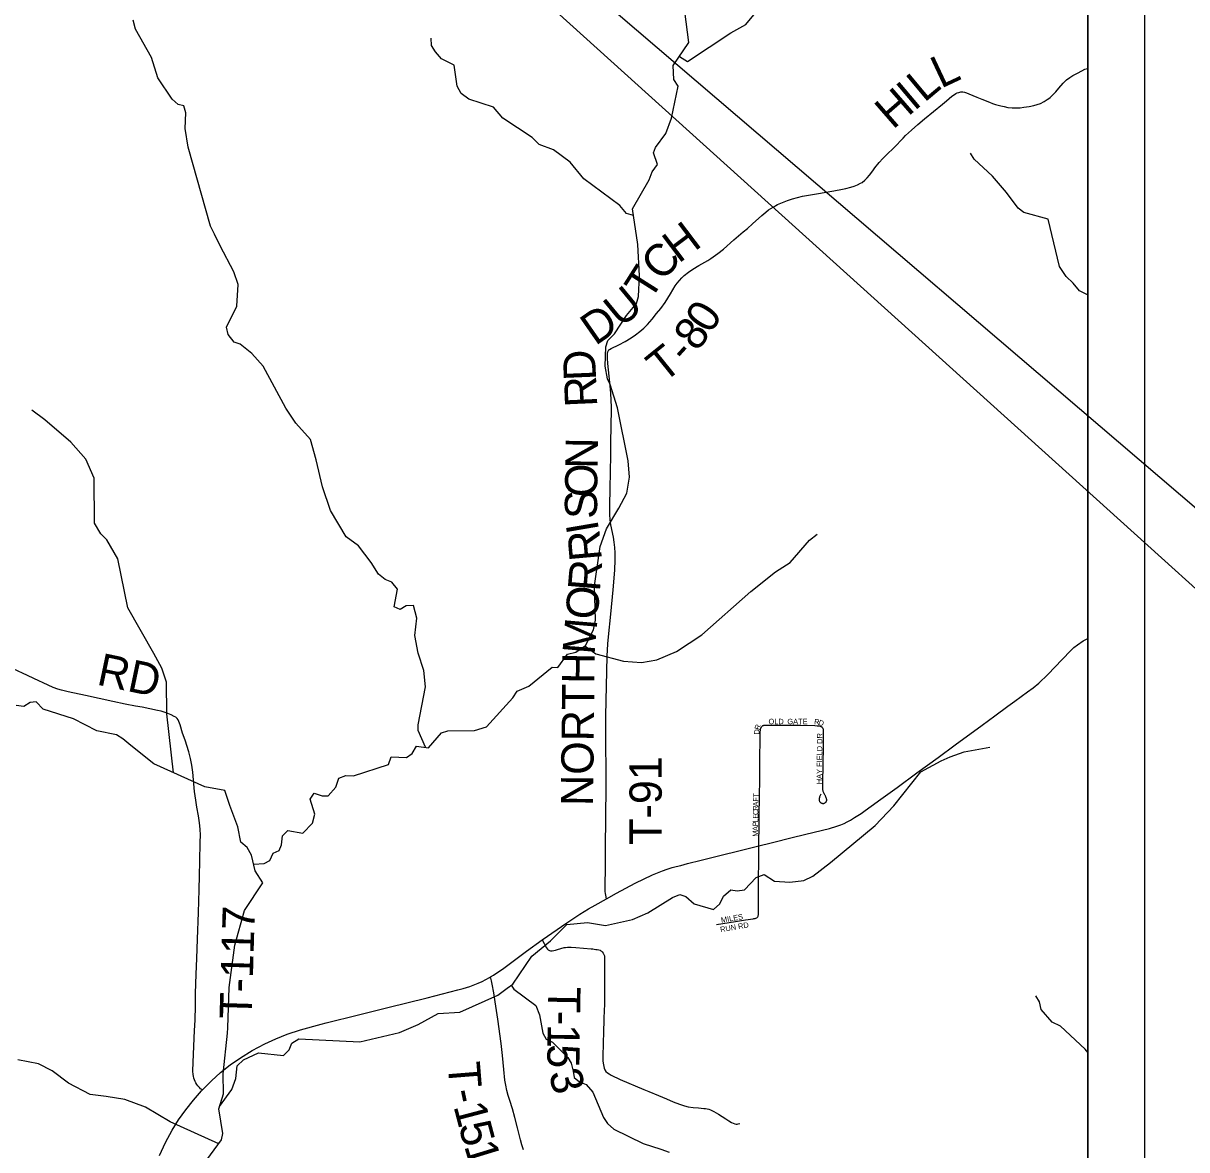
# Model space of a CAD drawing. Extents: x 0 to 34, y 0 to 22.
# Drawn here: x 7.525 to 9.575, y 16.31 to 18.295 of the extents above; entities that cross this region are included whole.
import ezdxf

# ---------------------------------------------------------------- set-up
doc = ezdxf.new("R2010")
doc.units = 0
for name, color, linetype in [('GM_X_County', 7, 'Continuous'), ('GM_X_Minor_River', 7, 'Continuous'), ('GM_X_State_Route', 7, 'Continuous'), ('GM_X_Township', 7, 'Continuous'), ('GM_X_Township_Road', 7, 'Continuous'), ('GM_X_Township_Road_Text', 7, 'Continuous'), ('GM_X_Township_Subdivision', 7, 'Continuous'), ('GM_X_Township_Subdivision_Text', 7, 'Continuous'), ('SH_Data', 7, 'Continuous')]:
    doc.layers.add(name, color=color, linetype=linetype)

msp = doc.modelspace()

# ---------------------------------------------------------------- linework, layer by layer
at = {"layer": 'GM_X_County'}
msp.add_lwpolyline([(7.0736, 21.2003), (2.6013, 21.2003), (2.6013, 14.4003), (9.4013, 14.4003), (9.4013, 21.1598)], dxfattribs=at)
at = {"layer": 'GM_X_Minor_River'}
for points in [[(8.6808, 18.2367), (8.6953, 18.228), (8.7713, 18.2784), (8.7977, 18.2929), (8.8207, 18.3207), (8.8495, 18.3402), (8.8638, 18.3467), (8.8752, 18.3479), (8.8881, 18.3521), (8.9145, 18.3738), (8.9303, 18.4008), (8.9544, 18.4256), (9.0262, 18.4749), (9.0455, 18.4962), (9.0612, 18.5312), (9.0657, 18.5441), (9.0807, 18.576), (9.1045, 18.5996), (9.1615, 18.6431), (9.1725, 18.6477)], [(7.9306, 16.8132), (7.9492, 16.8148), (7.959, 16.8197), (7.965, 16.8327), (7.9756, 16.8377), (7.9797, 16.8475), (7.9812, 16.8635), (7.991, 16.873), (8.0175, 16.8678), (8.0345, 16.8857), (8.0386, 16.9017), (8.0301, 16.9282), (8.0373, 16.9385), (8.0513, 16.9336), (8.0619, 16.9337), (8.0751, 16.9493), (8.0804, 16.9649), (8.0932, 16.9698), (8.1065, 16.9691), (8.1682, 16.9888), (8.1727, 17.0028), (8.1996, 17.0014), (8.2098, 17.0083), (8.2177, 17.0216), (8.2389, 17.0187), (8.2615, 17.045), (8.2725, 17.0484), (8.3195, 17.0487), (8.3411, 17.0556), (8.3875, 17.1066), (8.395, 17.118), (8.4154, 17.1269), (8.4566, 17.1608), (8.4668, 17.1601), (8.4834, 17.1837), (8.4985, 17.1872), (8.5151, 17.199), (8.5294, 17.2264), (8.5331, 17.2431), (8.5309, 17.3038), (8.5409, 17.3729), (8.5525, 17.4041), (8.5743, 17.441), (8.5882, 17.4672), (8.5926, 17.4953), (8.5906, 17.5241), (8.5719, 17.6174), (8.5585, 17.6587), (8.5543, 17.6685), (8.55, 17.6912), (8.551, 17.725), (8.5547, 17.7364), (8.5664, 17.7478), (8.5875, 17.7802), (8.6052, 17.8011), (8.6086, 17.814), (8.6107, 17.8501), (8.6078, 17.9051), (8.598, 17.968), (8.6273, 18.0194), (8.6326, 18.0334), (8.642, 18.0464), (8.6354, 18.0668), (8.6388, 18.0763), (8.6569, 18.1011), (8.6666, 18.128), (8.6785, 18.1842), (8.6708, 18.1964), (8.67, 18.2206), (8.6975, 18.2613), (8.688, 18.3341)], [(8.2333, 17.0195), (8.2206, 17.049), (8.2202, 17.0592), (8.2335, 17.126), (8.2303, 17.1545), (8.2203, 17.1852), (8.2145, 17.2162), (8.2178, 17.247), (8.212, 17.2693), (8.1995, 17.2689), (8.1885, 17.262), (8.1779, 17.2669), (8.1842, 17.2981), (8.1743, 17.3105), (8.1625, 17.315), (8.1503, 17.3245), (8.1377, 17.3449), (8.1156, 17.3744), (8.0936, 17.3902), (8.0657, 17.4364), (8.0518, 17.4784), (8.0406, 17.5262), (8.031, 17.5618), (8.0047, 17.5905), (7.9872, 17.617), (7.9474, 17.6911), (7.9272, 17.7134), (7.907, 17.73), (7.8964, 17.733), (7.8857, 17.7466), (7.8827, 17.7595), (7.901, 17.7968), (7.9031, 17.8351), (7.8955, 17.857), (7.8718, 17.9032), (7.8614, 17.9233), (7.8545, 17.9377), (7.8149, 18.0767), (7.8098, 18.1097), (7.8108, 18.1374), (7.8073, 18.1495), (7.7975, 18.1521), (7.7868, 18.1616), (7.7616, 18.199), (7.7505, 18.2346), (7.7226, 18.2849), (7.7183, 18.3008)], [(8.5997, 17.9567), (8.5878, 17.96), (8.5756, 17.974), (8.5125, 18.0208), (8.4881, 18.0506), (8.4588, 18.0721), (8.4337, 18.0815), (8.4215, 18.0939), (8.3698, 18.1278), (8.3531, 18.1475), (8.3098, 18.1613), (8.2961, 18.1715), (8.2892, 18.1844), (8.2838, 18.2212), (8.2613, 18.2324), (8.2511, 18.2449), (8.2438, 18.2559), (8.2434, 18.2688)], [(9.4013, 17.8162), (9.3859, 17.8235), (9.3745, 17.8371), (9.3623, 17.8488), (9.3504, 17.8666), (9.3307, 17.95), (9.2875, 17.9616), (9.2776, 17.9691), (9.2574, 17.9967), (9.2326, 18.0255), (9.1999, 18.056), (9.1937, 18.0663)], [(7.7895, 16.9746), (7.7778, 17.0784), (7.7772, 17.1342), (7.7687, 17.1588), (7.7546, 17.1845), (7.7087, 17.2651), (7.6913, 17.3515), (7.6718, 17.3852), (7.6615, 17.3958), (7.65, 17.4143), (7.6493, 17.4936), (7.6347, 17.5269), (7.6084, 17.5571), (7.5624, 17.5964), (7.5396, 17.6137)], [(8.5143, 17.1984), (8.5334, 17.1843), (8.5823, 17.1713), (8.6142, 17.1687), (8.6411, 17.1734), (8.6755, 17.188), (8.7205, 17.2174), (8.8065, 17.2937), (8.8503, 17.3288), (8.876, 17.3448), (8.91, 17.3844), (8.9236, 17.3951)], [(7.8888, 16.9165), (7.88, 16.9431), (7.8447, 16.9497), (7.7547, 16.9903), (7.7144, 17.0223), (7.7003, 17.034), (7.6889, 17.0412), (7.6544, 17.0486), (7.6133, 17.0693), (7.5594, 17.0865), (7.5476, 17.0994), (7.5367, 17.0982), (7.5257, 17.0913), (7.512, 17.0931)], [(7.8706, 16.3864), (7.8923, 16.4165), (7.8994, 16.4359), (7.9016, 16.4583), (7.9129, 16.4686), (7.939, 16.4809), (7.983, 16.4761), (7.9932, 16.4864), (7.9976, 16.4982), (8.0101, 16.5058), (8.1174, 16.5003), (8.1878, 16.5165), (8.2207, 16.5307), (8.2555, 16.5502), (8.2941, 16.5527), (8.3607, 16.5826), (8.3773, 16.5948), (8.3871, 16.602), (8.4207, 16.6515), (8.4535, 16.6782), (8.4822, 16.7068), (8.5189, 16.7104), (8.5508, 16.7052), (8.5981, 16.7161), (8.625, 16.7279), (8.6688, 16.7547), (8.6817, 16.7597), (8.6919, 16.7563), (8.7068, 16.7435), (8.7409, 16.7338), (8.7519, 16.7437), (8.7582, 16.757), (8.7711, 16.7684), (8.7824, 16.7662), (8.7957, 16.7682), (8.8161, 16.7899), (8.8301, 16.7952), (8.8483, 16.7832), (8.8756, 16.7814), (8.8999, 16.7846), (8.9157, 16.7922), (8.9471, 16.8166), (9.026, 16.8815), (9.0588, 16.9161), (9.1063, 16.9759), (9.1418, 16.9954), (9.1577, 17.0023), (9.1823, 17.0115), (9.2278, 17.0193)], [(7.8271, 16.2637), (7.8741, 16.3277), (7.876, 16.3387), (7.8693, 16.3823), (7.8775, 16.4089), (7.877, 16.4442), (7.8846, 16.5155), (7.885, 16.525), (7.8873, 16.596), (7.8972, 16.6707), (7.9147, 16.7315), (7.9467, 16.7806), (7.9333, 16.8018), (7.9267, 16.8295), (7.9191, 16.8427), (7.9077, 16.8521), (7.9026, 16.879), (7.8888, 16.9165)], [(8.3845, 16.6001), (8.3891, 16.5933), (8.4275, 16.5643), (8.434, 16.548), (8.4402, 16.5154), (8.446, 16.5048), (8.457, 16.4999), (8.484, 16.4727), (8.4901, 16.4629), (8.4936, 16.4485), (8.4952, 16.4375), (8.5047, 16.4296), (8.5165, 16.4254), (8.5283, 16.4115), (8.547, 16.3672), (8.5539, 16.3566), (8.5653, 16.3464), (8.617, 16.3212), (8.6481, 16.3111), (8.6629, 16.3058)], [(9.4013, 16.4812), (9.3959, 16.4874), (9.3521, 16.5278), (9.3376, 16.535), (9.3182, 16.5573), (9.3151, 16.5709), (9.3086, 16.5815)], [(7.869, 16.3207), (7.7834, 16.3591), (7.7397, 16.3851), (7.7036, 16.3986), (7.6706, 16.4041), (7.6422, 16.4078), (7.6042, 16.4277), (7.5753, 16.4492), (7.5514, 16.4616), (7.5149, 16.4687)]]:
    msp.add_lwpolyline(points, dxfattribs=at)
at = {"layer": 'GM_X_State_Route'}
for points in [[(8.0585, 16.5337), (8.1156, 16.5479), (8.1668, 16.5608), (8.2362, 16.5779), (8.2904, 16.5917), (8.2997, 16.5942), (8.3112, 16.598), (8.32, 16.6011), (8.3264, 16.6039), (8.3332, 16.6068), (8.3397, 16.61), (8.346, 16.6136), (8.3479, 16.6147), (8.3534, 16.6181), (8.3714, 16.6304), (8.4113, 16.66), (8.4389, 16.6801), (8.4823, 16.7101), (8.5056, 16.7255), (8.5208, 16.7348), (8.5321, 16.7414), (8.5522, 16.7526), (8.57, 16.7625), (8.6028, 16.78), (8.6336, 16.7945), (8.6508, 16.8015), (8.6591, 16.8044), (8.6681, 16.8075), (8.6753, 16.8093), (8.6833, 16.8113), (8.6952, 16.8144), (8.719, 16.8206), (8.8206, 16.8456), (8.8427, 16.851), (8.8818, 16.8607), (8.918, 16.8696), (8.9452, 16.8763), (8.958, 16.8802), (8.965, 16.8827), (8.971, 16.885), (8.9766, 16.8879), (8.9822, 16.8912), (8.9893, 16.8954), (8.9954, 16.8992), (9.0009, 16.9026), (9.0081, 16.9078), (9.0188, 16.9157), (9.0358, 16.9278), (9.0642, 16.9486), (9.099, 16.9741), (9.137, 17.0015), (9.1669, 17.0237), (9.2143, 17.0585), (9.2368, 17.075), (9.2592, 17.0917), (9.2717, 17.1009), (9.2944, 17.117), (9.3043, 17.1244), (9.3139, 17.1324), (9.3297, 17.1474), (9.3554, 17.1743), (9.3705, 17.1898), (9.376, 17.1951), (9.3822, 17.1998), (9.3923, 17.2068), (9.4004, 17.2112), (9.4013, 17.2116)], [(7.7648, 16.3002), (7.7753, 16.3227), (7.787, 16.3446), (7.7983, 16.3631), (7.8108, 16.3808), (7.8243, 16.3978), (7.8388, 16.4139), (7.8403, 16.4155), (7.8562, 16.4315), (7.8723, 16.4461), (7.8893, 16.4596), (7.9071, 16.472), (7.9282, 16.485), (7.95, 16.4968), (7.9697, 16.5059), (7.9899, 16.5138), (8.0134, 16.5216), (8.0493, 16.5314), (8.0585, 16.5337)]]:
    msp.add_lwpolyline(points, dxfattribs=at)
at = {"layer": 'GM_X_Township'}
msp.add_line((9.4013, 16.1226), (9.4013, 21.1598), dxfattribs=at)
at = {"layer": 'GM_X_Township_Road'}
for points in [[(8.5546, 17.7165), (8.5551, 17.7176), (8.5558, 17.7188), (8.5567, 17.7197), (8.5576, 17.7205), (8.5603, 17.7221), (8.5743, 17.7287), (8.5852, 17.7347), (8.5958, 17.7411), (8.6036, 17.7462), (8.611, 17.7518), (8.618, 17.758), (8.6246, 17.7646), (8.6328, 17.7739), (8.6406, 17.7836), (8.6481, 17.7928), (8.6555, 17.8032), (8.6651, 17.8187), (8.6733, 17.8323), (8.6769, 17.8374), (8.6807, 17.8422), (8.6849, 17.8467), (8.6894, 17.8509), (8.6967, 17.8566), (8.7043, 17.8618), (8.7149, 17.8682), (8.731, 17.8774), (8.7362, 17.8807), (8.7486, 17.8897), (8.7582, 17.8974), (8.7769, 17.9135), (8.7934, 17.9274), (8.8005, 17.9335), (8.8097, 17.9417), (8.8258, 17.9564), (8.8328, 17.9625), (8.8378, 17.9662), (8.8457, 17.9712), (8.8539, 17.9756), (8.8623, 17.9795), (8.871, 17.9829), (8.8798, 17.9859), (8.8888, 17.9884), (8.8979, 17.9904), (8.9223, 17.9948), (8.9529, 18.0001), (8.9681, 18.0028), (8.9712, 18.0034), (8.9742, 18.004), (8.9831, 18.0063), (8.9889, 18.0081), (8.9946, 18.0104), (9.0001, 18.0132), (9.0027, 18.0149), (9.0076, 18.0187), (9.0119, 18.023), (9.0159, 18.0278), (9.0215, 18.0352), (9.0252, 18.0402), (9.033, 18.0498), (9.0392, 18.0567), (9.0457, 18.0634), (9.0591, 18.0764), (9.0748, 18.0926), (9.0793, 18.0975), (9.0899, 18.107), (9.1011, 18.1169), (9.1129, 18.127), (9.1441, 18.1526), (9.1512, 18.1587), (9.1607, 18.1666), (9.1655, 18.1699), (9.1679, 18.1712), (9.1704, 18.1724), (9.1732, 18.1734), (9.1767, 18.1741), (9.1799, 18.1741), (9.1831, 18.1737), (9.1866, 18.1729), (9.1908, 18.1711), (9.1977, 18.1679), (9.2047, 18.1648), (9.2138, 18.1612), (9.227, 18.1562), (9.2326, 18.154), (9.2377, 18.1523), (9.2469, 18.1496), (9.253, 18.1483), (9.2595, 18.147), (9.2674, 18.1462), (9.2744, 18.1461), (9.2815, 18.1464), (9.2878, 18.1471), (9.2968, 18.1484), (9.3055, 18.1503), (9.3114, 18.152), (9.3169, 18.1541), (9.3233, 18.1574), (9.3289, 18.1606), (9.3319, 18.1626), (9.334, 18.1644), (9.3384, 18.1688), (9.3439, 18.1746), (9.3493, 18.1809), (9.3568, 18.1899), (9.363, 18.1953), (9.3689, 18.1994), (9.3742, 18.203), (9.382, 18.2075), (9.3898, 18.2113), (9.3954, 18.2141), (9.3996, 18.2155), (9.4013, 18.2158)], [(8.5522, 16.7526), (8.5509, 16.7586), (8.5504, 16.7617), (8.5501, 16.7653), (8.55, 16.7715), (8.5501, 16.7807), (8.5503, 16.8023), (8.5504, 16.8208), (8.5504, 16.8363), (8.5507, 16.858), (8.551, 16.8797), (8.5513, 16.9106), (8.5515, 16.9354), (8.5517, 16.954), (8.5517, 16.9788), (8.5516, 16.9943), (8.5513, 17.0097), (8.5513, 17.0747), (8.5533, 17.1799), (8.5546, 17.2016), (8.5556, 17.2139), (8.56, 17.2539), (8.5642, 17.2971), (8.5667, 17.3312), (8.5675, 17.3498), (8.5675, 17.3622), (8.5671, 17.3715), (8.5661, 17.3807), (8.5646, 17.3899), (8.5599, 17.4111), (8.5586, 17.4203), (8.5579, 17.4295), (8.5579, 17.4451), (8.5585, 17.4761), (8.5592, 17.504), (8.5597, 17.535), (8.5602, 17.5598), (8.5604, 17.5815), (8.5609, 17.6186), (8.5607, 17.631), (8.5601, 17.6434), (8.5583, 17.662), (8.5548, 17.6959), (8.554, 17.7052), (8.5538, 17.7105), (8.5539, 17.7125), (8.5541, 17.7144), (8.5546, 17.7165)], [(7.8275, 16.4304), (7.8273, 16.4307), (7.8261, 16.4336), (7.8251, 16.4365), (7.8244, 16.4396), (7.8239, 16.4426), (7.8235, 16.4488), (7.8237, 16.4643), (7.8264, 16.5202), (7.8273, 16.5388), (7.8278, 16.5636), (7.8282, 16.5853), (7.8293, 16.6194), (7.8302, 16.6474), (7.8314, 16.6815), (7.8333, 16.728), (7.8344, 16.7683), (7.835, 16.7932), (7.8355, 16.818), (7.836, 16.8303), (7.8362, 16.8396), (7.8366, 16.852), (7.8368, 16.8647), (7.8363, 16.8751), (7.8352, 16.8862), (7.8331, 16.8985), (7.8305, 16.9137), (7.8287, 16.9259), (7.8266, 16.9413), (7.8233, 16.9753), (7.8218, 16.9876), (7.8192, 16.9997), (7.8162, 17.0114), (7.8097, 17.0321), (7.8052, 17.0442), (7.8008, 17.0591), (7.7988, 17.065), (7.7974, 17.0677), (7.7955, 17.0702), (7.7932, 17.0723), (7.7906, 17.0739), (7.785, 17.0765), (7.7763, 17.08), (7.7675, 17.0829), (7.7614, 17.0844), (7.7342, 17.0898), (7.7221, 17.092), (7.7039, 17.0955), (7.6826, 17.0999), (7.6342, 17.1106), (7.6038, 17.117), (7.5917, 17.1199), (7.5858, 17.1217), (7.5771, 17.125), (7.5685, 17.1287), (7.5433, 17.1404), (7.5321, 17.1457), (7.5069, 17.1579)], [(8.4389, 16.6801), (8.4424, 16.6735), (8.4464, 16.6659), (8.4482, 16.6634), (8.4494, 16.6624), (8.4506, 16.6617), (8.452, 16.6613), (8.4535, 16.6609), (8.4565, 16.6608), (8.4596, 16.6613), (8.4627, 16.662), (8.4657, 16.6629), (8.4716, 16.6648), (8.4775, 16.6664), (8.4803, 16.6668), (8.4837, 16.667), (8.4898, 16.667), (8.498, 16.6663), (8.5251, 16.6644), (8.528, 16.6641), (8.5308, 16.6636), (8.5336, 16.6632), (8.536, 16.6629), (8.5387, 16.6623), (8.541, 16.6616), (8.5422, 16.6609), (8.5432, 16.6603), (8.544, 16.6596), (8.5446, 16.6589), (8.5464, 16.6566), (8.5477, 16.6541), (8.5485, 16.6516), (8.5488, 16.6485), (8.549, 16.6456), (8.549, 16.6394), (8.5487, 16.6301), (8.5486, 16.5655), (8.5484, 16.5562), (8.5478, 16.5406), (8.547, 16.5157), (8.5466, 16.5002), (8.546, 16.4722), (8.5461, 16.466), (8.5469, 16.4598), (8.5475, 16.4567), (8.5484, 16.4538), (8.5496, 16.4509), (8.5512, 16.4483), (8.5539, 16.4459), (8.5569, 16.4439), (8.5608, 16.4415), (8.5763, 16.4342), (8.6178, 16.4166), (8.6266, 16.413), (8.6438, 16.4058), (8.658, 16.3996), (8.6695, 16.3948), (8.6811, 16.3903), (8.6899, 16.3874), (8.696, 16.3859), (8.7052, 16.3844), (8.7145, 16.3838), (8.7238, 16.3831), (8.7269, 16.3827), (8.7329, 16.3814), (8.7358, 16.3803), (8.7414, 16.3777), (8.7494, 16.373), (8.7623, 16.3645), (8.7676, 16.3613), (8.7727, 16.3583), (8.7754, 16.3571), (8.7783, 16.3561), (8.7808, 16.3555), (8.7827, 16.3555), (8.7843, 16.3556), (8.7873, 16.3564)], [(8.4062, 16.31), (8.4031, 16.3188), (8.4005, 16.3278), (8.3953, 16.3489), (8.3909, 16.3671), (8.3867, 16.382), (8.3819, 16.3968), (8.3791, 16.4057), (8.3769, 16.4147), (8.3749, 16.4238), (8.3734, 16.433), (8.3713, 16.4514), (8.3693, 16.4761), (8.3669, 16.4976), (8.3609, 16.5404), (8.3587, 16.5558), (8.3564, 16.5711), (8.3536, 16.5864), (8.3508, 16.6017), (8.3495, 16.6078), (8.3479, 16.6147)], [(7.8403, 16.4155), (7.8371, 16.4176), (7.8351, 16.4196), (7.8321, 16.4228), (7.8304, 16.4253), (7.8287, 16.428), (7.8275, 16.4304)]]:
    msp.add_lwpolyline(points, dxfattribs=at)
at = {"layer": 'GM_X_Township_Subdivision'}
for points in [[(8.8267, 17.0566), (8.8274, 17.0571), (8.828, 17.0575), (8.8284, 17.0577), (8.8291, 17.0579), (8.8297, 17.0581), (8.8306, 17.0583), (8.8316, 17.0584), (8.8331, 17.0586), (8.8352, 17.0586), (8.8422, 17.0586), (8.8532, 17.0584), (8.8724, 17.0581), (8.8943, 17.0581), (8.9193, 17.0576), (8.9233, 17.0574), (8.9256, 17.0571), (8.9273, 17.0569), (8.9288, 17.0566), (8.93, 17.0562), (8.9308, 17.0558), (8.9315, 17.0554), (8.9319, 17.055), (8.9325, 17.0545)], [(8.8206, 16.8456), (8.8212, 16.8862), (8.8214, 16.9036), (8.8217, 16.9273), (8.8223, 16.9684), (8.8226, 16.9961), (8.8229, 17.0373), (8.823, 17.0423), (8.8231, 17.0452), (8.8232, 17.0467), (8.8234, 17.0489), (8.8235, 17.0498), (8.8236, 17.0509), (8.8238, 17.0518), (8.824, 17.0527), (8.8244, 17.0535), (8.8248, 17.0543), (8.8253, 17.0551), (8.8261, 17.056), (8.8267, 17.0566)], [(8.9301, 16.937), (8.929, 16.9345), (8.9284, 16.9334), (8.9279, 16.9321), (8.9276, 16.9311), (8.9274, 16.9305), (8.9272, 16.9298), (8.9271, 16.929), (8.927, 16.9283), (8.9269, 16.9274), (8.927, 16.927), (8.9271, 16.9263), (8.9272, 16.9257), (8.9275, 16.9246), (8.9278, 16.924), (8.9283, 16.9232), (8.9289, 16.9226), (8.9295, 16.922), (8.9301, 16.9216), (8.9307, 16.9213), (8.9314, 16.921), (8.9321, 16.9208), (8.9327, 16.9206), (8.9334, 16.9205), (8.9341, 16.9205), (8.935, 16.9206), (8.9357, 16.9207), (8.9366, 16.921), (8.9373, 16.9214), (8.938, 16.9218), (8.9386, 16.9224), (8.9391, 16.9229), (8.9395, 16.9236), (8.9398, 16.9242), (8.9401, 16.9251), (8.9403, 16.9257), (8.9404, 16.9264), (8.9404, 16.9269), (8.9403, 16.9276), (8.9402, 16.9282), (8.9399, 16.9294), (8.9395, 16.9305), (8.939, 16.9318), (8.9384, 16.933), (8.9379, 16.934), (8.9374, 16.9347), (8.9363, 16.9368), (8.9358, 16.9376), (8.9351, 16.9392), (8.9346, 16.9404), (8.9342, 16.9414), (8.9339, 16.9425), (8.9337, 16.9437), (8.9336, 16.9449), (8.9335, 16.9462), (8.9334, 16.9476), (8.9334, 16.9501), (8.9334, 16.9619), (8.9338, 16.9835), (8.9345, 17.0264), (8.9348, 17.0433), (8.9348, 17.0452), (8.9348, 17.0467), (8.9347, 17.0476), (8.9347, 17.0486), (8.9346, 17.0494), (8.9344, 17.0505), (8.9341, 17.0516), (8.9338, 17.0524), (8.9334, 17.0532), (8.933, 17.0539), (8.9325, 17.0545)], [(8.746, 16.7071), (8.7796, 16.7125), (8.7974, 16.7151), (8.8109, 16.7173), (8.812, 16.7175), (8.814, 16.7179), (8.8154, 16.7182), (8.8171, 16.7188), (8.8179, 16.7193), (8.8185, 16.7199), (8.8189, 16.7204), (8.8195, 16.7215), (8.8198, 16.7227), (8.82, 16.724), (8.8202, 16.7255), (8.8202, 16.7277), (8.8202, 16.7298), (8.8201, 16.7443), (8.8201, 16.7597), (8.8206, 16.8456)]]:
    msp.add_lwpolyline(points, dxfattribs=at)
at = {"layer": 'SH_Data'}
for p, q in [((9.5, 21.2997), (9.5, 14.2997)), ((9.4, 21.1997), (9.4, 14.3997))]:
    msp.add_line(p, q, dxfattribs=at)
msp.add_lwpolyline([(6.619, 19.9811), (10.5909, 16.3957), (10.5909, 16.5853)], close=True, dxfattribs=at)

# ---------------------------------------------------------------- texts
at = {"layer": 'GM_X_Township_Road_Text'}
for s, height, rotation, p in [('L', 0.0568, 25.1601, (9.1416, 18.1797)), ('L', 0.0568, 39.8961, (9.1122, 18.1545)), ('I', 0.0568, 40.1534, (9.0944, 18.1395)), ('H', 0.0568, 41.0533, (9.0569, 18.1068)), ('H', 0.0568, 37.1606, (8.6793, 17.871)), ('C', 0.0568, 48.4352, (8.6505, 17.8381)), ('T', 0.0568, 57.6853, (8.6292, 17.8041)), ('U', 0.0568, 39.5193, (8.5777, 17.7576)), ('0', 0.0568, 56.6928, (8.735, 17.7461)), ('D', 0.0568, 34.8419, (8.5326, 17.726)), ('8', 0.0568, 53.3526, (8.7121, 17.7151)), ('D', 0.0568, 92.4049, (8.5341, 17.6664)), ('T', 0.0568, 38.8974, (8.6525, 17.6598)), ('-', 0.0568, 47.8427, (8.6926, 17.6932)), ('R', 0.0568, 92.5574, (8.5362, 17.6199)), ('N', 0.0568, 89.1585, (8.5365, 17.51)), ('O', 0.0568, 89.1731, (8.5358, 17.46)), ('S', 0.0568, 90.0618, (8.5358, 17.4219)), ('I', 0.0568, 99.6742, (8.5395, 17.4014)), ('R', 0.0568, 95.0317, (8.5443, 17.3499)), ('R', 0.0568, 85.3102, (8.5405, 17.2929)), ('O', 0.0568, 85.2195, (8.5363, 17.243)), ('M', 0.0568, 85.2155, (8.5312, 17.1815)), ('RD', 0.05682, 348.1099, (7.6523, 17.1302)), ('NORTH', 0.05682, 89.4026, (8.5286, 16.9157)), ('T-91', 0.05682, 90, (8.6496, 16.8475)), ('T-117', 0.05682, 88.3278, (7.9271, 16.5404)), ('T', 0.0568, 268.9585, (8.4499, 16.5978)), ('-', 0.0568, 268.9797, (8.4491, 16.5553)), ('1', 0.0568, 269.0931, (8.4487, 16.5319)), ('5', 0.0568, 269.6277, (8.4481, 16.4963)), ('T', 0.0568, 274.5433, (8.2724, 16.463)), ('3', 0.0568, 284.8766, (8.45, 16.445)), ('-', 0.0568, 281.7601, (8.2769, 16.4129)), ('1', 0.0568, 284.7259, (8.2824, 16.387)), ('5', 0.0568, 284.9849, (8.2913, 16.3528)), ('1', 0.0568, 286.9476, (8.301, 16.317))]:
    msp.add_text(s, height=height, rotation=rotation, dxfattribs=at).set_placement(p)
at = {"layer": 'GM_X_Township_Subdivision_Text'}
for s, rotation, p in [('R', 71.3654, (8.8217, 17.0492)), ('OLD', 0, (8.8377, 17.0601)), ('GATE', 0, (8.871, 17.0601)), ('R', 353.8207, (8.9178, 17.0601)), ('D', 339.1932, (8.9246, 17.0595)), ('D', 89.3224, (8.8217, 17.0417)), ('HAY FIELD DR', 89.4035, (8.9318, 16.9542)), ('T', 86.4458, (8.8202, 16.9299)), ('R', 89.2714, (8.8198, 16.9075)), ('A', 89.2568, (8.8199, 16.915)), ('F', 88.0053, (8.82, 16.9233)), ('C', 89.2576, (8.8197, 16.9)), ('L', 89.2623, (8.8195, 16.8867)), ('E', 89.2623, (8.8196, 16.8934)), ('A', 89.2568, (8.8193, 16.8717)), ('P', 89.2623, (8.8194, 16.88)), ('M', 89.2713, (8.8192, 16.8617)), ('RUN RD', 9.8177, (8.7534, 16.6934)), ('MILES', 9.4623, (8.7548, 16.7101))]:
    msp.add_text(s, height=0.00947, rotation=rotation, dxfattribs=at).set_placement(p)

doc.saveas('drawing.dxf')
